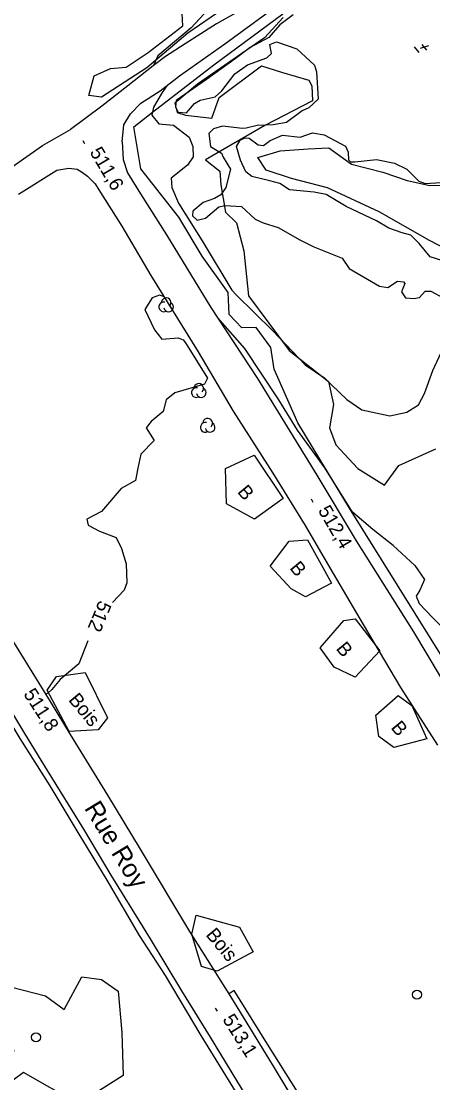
# Model space of a CAD drawing. Extents: x 347312 to 350503, y 6073086 to 6076432.
# Drawn here: x 348774 to 348863.2, y 6075462.2 to 6075692.2 of the extents above; entities that cross this region are included whole.
import ezdxf

# ---------------------------------------------------------------- set-up
doc = ezdxf.new("R2010")
doc.units = 0
for name, color, linetype in [('Level 1', 7, 'Continuous'), ('Level 2', 7, 'Continuous'), ('Level 21', 7, 'Continuous'), ('Level 22', 7, 'Continuous'), ('Level 3', 7, 'Continuous'), ('Level 36', 7, 'Continuous'), ('Level 4', 7, 'Continuous'), ('Level 44', 7, 'Continuous')]:
    doc.layers.add(name, color=color, linetype=linetype)

msp = doc.modelspace()

# ---------------------------------------------------------------- linework, layer by layer
at = {"layer": 'Level 1'}
for points in [[(348792.67, 6075717.75), (348797.14, 6075713.74), (348799.35, 6075711.05), (348800.45, 6075708.11), (348801.76, 6075705.87), (348803.97, 6075703.98), (348807.41, 6075702.03), (348811.66, 6075699.8), (348812.76, 6075698.76), (348814.14, 6075697.19), (348813.53, 6075693.76), (348810.82, 6075690.76), (348803.59, 6075684.69), (348802.71, 6075682.76), (348802.76, 6075682.69)], [(348805.5, 6075678.23), (348804.5, 6075676.72), (348802.64, 6075673.61), (348802.31, 6075671.83), (348803.82, 6075669.93), (348806.97, 6075669.68), (348810.36, 6075667.08), (348811.2, 6075665.07), (348811.24, 6075662.85), (348810.04, 6075661.03), (348806.44, 6075658.19), (348806.62, 6075656.16), (348808.04, 6075652.75), (348813.18, 6075644.61), (348819.65, 6075633.95), (348820.58, 6075632.93), (348828.51, 6075625.14), (348834.22, 6075619.11), (348835.5, 6075617.77), (348839.8, 6075614.87), (348841.31, 6075613.33), (348844.52, 6075610.21), (348847.78, 6075608.02), (348853.89, 6075606.68), (348857.51, 6075607.5), (348860.05, 6075609.08), (348861.34, 6075611.51), (348863.16, 6075616.48), (348865.94, 6075622.47)]]:
    msp.add_lwpolyline(points, dxfattribs=at)
at = {"layer": 'Level 2'}
for points in [[(348805, 6075632.44), (348803.94, 6075632.83), (348802.37, 6075632.27), (348800.78, 6075629.75), (348802.83, 6075625.3), (348804.46, 6075623.27), (348808.02, 6075623.6), (348809.06, 6075623.18), (348809.61, 6075622.51), (348814.37, 6075614.82), (348813.68, 6075613.57), (348807.29, 6075611.65), (348805.38, 6075610.15), (348804.74, 6075607.66), (348802.11, 6075605.48), (348801.03, 6075604.06), (348802.79, 6075601.32), (348799.88, 6075598.39), (348799.27, 6075595.32), (348798.74, 6075592.71), (348795.61, 6075590.94), (348791.41, 6075585.95), (348788.17, 6075584.32), (348788.46, 6075582.98), (348790.93, 6075581.73), (348794.54, 6075580.3), (348795.68, 6075577.94), (348796.73, 6075574.6), (348796.84, 6075570.49), (348796.28, 6075568.9), (348793.78, 6075566.23)], [(348854.6, 6075578.62), (348850.18, 6075582.02), (348845.8, 6075585.83), (348839.77, 6075595.4), (348833.86, 6075603.57), (348829.82, 6075610.13), (348822.46, 6075621.3), (348816.55, 6075627.95)], [(348854.6, 6075578.62), (348859.24, 6075574.25), (348861.34, 6075571.22), (348860.33, 6075568.93), (348859.57, 6075567.63), (348860.21, 6075566.05), (348863.1, 6075563.01), (348866.99, 6075559.08), (348871.48, 6075552.33), (348879.61, 6075540.67), (348884.92, 6075531.83), (348886.44, 6075529.65)], [(348788.4, 6075557.93), (348786.45, 6075552.94), (348782.39, 6075549.58), (348780.62, 6075547.36), (348779.73, 6075546.62), (348779.32, 6075546.4)]]:
    msp.add_lwpolyline(points, dxfattribs=at)
at = {"layer": 'Level 21'}
for points in [[(348820.43, 6075693.97), (348816.29, 6075691.6), (348809.51, 6075687.33), (348805.26, 6075684.55), (348802.56, 6075682.54), (348797.05, 6075678.2), (348791.45, 6075673.78), (348784.65, 6075668.74)], [(348795.88, 6075666.04), (348796.22, 6075669.74), (348797.63, 6075672.12), (348799.87, 6075674.42), (348804.07, 6075677.15), (348808.28, 6075680.34), (348818.12, 6075687.29), (348828.28, 6075694.74)], [(348619.66, 6075553.87), (348630.41, 6075564.21), (348642.32, 6075573.7), (348654.32, 6075582.45), (348666.87, 6075591.81), (348671.89, 6075594.95), (348677.61, 6075598.53), (348683.84, 6075602.72), (348697.14, 6075610.9), (348710.9, 6075619.61), (348726.09, 6075629.95), (348739.55, 6075638.85), (348753.52, 6075648.41), (348766.38, 6075656.75), (348778.57, 6075665.28), (348784.65, 6075668.74)], [(348795.88, 6075666.04), (348796.06, 6075662.21), (348797.02, 6075659.33), (348799.81, 6075654.82), (348805.45, 6075645.9), (348815.1, 6075630.18), (348825.15, 6075614.78), (348838.03, 6075593.86), (348846.54, 6075579.59), (348858.99, 6075559.88), (348870.32, 6075540.88), (348878.71, 6075527.02), (348888.64, 6075510.69), (348898.24, 6075494.76), (348906.45, 6075482.02), (348910.6, 6075477.5), (348912.89, 6075476.47), (348924.17, 6075478.22), (348938.88, 6075486.8), (348955.83, 6075497.3), (348969.56, 6075505.52), (348975.65, 6075508.61), (348976.73, 6075508.67), (348977.96, 6075508.19)], [(348773.4, 6075654.7), (348781.7, 6075659.93), (348784.29, 6075660.35), (348786.08, 6075660.11), (348787.25, 6075659.43), (348788.32, 6075658.59), (348789.98, 6075656.97), (348790.77, 6075655.67), (348795.75, 6075647.79), (348802.09, 6075637.13), (348812.36, 6075620.57), (348819.93, 6075607.7), (348828.48, 6075594.29), (348835.49, 6075582.9), (348840.85, 6075573.76), (348848.07, 6075561.5), (348856.15, 6075547.84), (348864.2, 6075535.29)], [(348836.72, 6075452.34), (348828.46, 6075466.15), (348820.81, 6075478.58), (348819.03, 6075481.41), (348810.51, 6075494.91), (348799.83, 6075512.79), (348792.73, 6075524.47), (348784.65, 6075537.6), (348780.34, 6075544.76), (348769.89, 6075561.63)], [(348822.91, 6075458.94), (348815.03, 6075472.01), (348808.76, 6075482.06), (348801.99, 6075493.35), (348793.44, 6075507.13), (348787.54, 6075517.11), (348779.67, 6075529.81), (348774.78, 6075537.84), (348769.21, 6075547.05)]]:
    msp.add_lwpolyline(points, dxfattribs=at)
at = {"layer": 'Level 22'}
for points in [[(348837.61, 6075425.75), (348836.85, 6075426.95), (348838.29, 6075428.37), (348838.53, 6075429.25), (348838.45, 6075430.53), (348835.14, 6075436.13), (348828.18, 6075447.56), (348820.39, 6075460.34), (348812.99, 6075472.38), (348805.23, 6075485.39), (348799.62, 6075494.11), (348792.63, 6075506.03), (348786.31, 6075516.42), (348780.25, 6075526.49), (348773.72, 6075536.76), (348766.95, 6075547.96), (348764.72, 6075551), (348763.64, 6075551.84), (348762.61, 6075552.18), (348761.64, 6075552.35), (348760.24, 6075551.94), (348756.72, 6075549.93), (348749.31, 6075544.99), (348744.96, 6075541.98)], [(348901.69, 6075464.54), (348900.87, 6075465.84), (348895.33, 6075462.45), (348884.32, 6075455.81), (348874.88, 6075449.87), (348864.55, 6075443.73), (348853.03, 6075436.67), (348850.81, 6075435.72), (348850.11, 6075435.75), (348849.01, 6075436.26), (348848.15, 6075437.2), (348847.06, 6075438.41), (348840.37, 6075449.16), (348834.18, 6075459.65), (348826.97, 6075471.1), (348820.1, 6075482.15), (348819.03, 6075481.41)]]:
    msp.add_lwpolyline(points, dxfattribs=at)
at = {"layer": 'Level 3'}
for p, q in [((348859.13, 6075686.67), (348860.15, 6075685.44)), ((348862.23, 6075686.84), (348860.4, 6075686.29)), ((348860.81, 6075687.15), (348861.8, 6075685.95)), ((348787.3, 6075666.37), (348787.71, 6075665.68)), ((348836.78, 6075588.69), (348837.19, 6075588)), ((348816, 6075478.36), (348816.43, 6075477.68))]:
    msp.add_line(p, q, dxfattribs=at)
at = {"layer": 'Level 36'}
for centre in [(348859.74, 6075481.26), (348777.19, 6075472.01)]:
    msp.add_circle(centre, 1, dxfattribs=at)
at = {"layer": 'Level 4'}
for points in [[(348832.88, 6075693.57), (348830.04, 6075691.44), (348827.64, 6075688.71), (348823.6, 6075686.48), (348820.33, 6075684.07), (348814.14, 6075679.54), (348807.58, 6075675), (348807.4, 6075673.58), (348808, 6075672.5), (348809.8, 6075672.34), (348811.51, 6075674.36), (348812.78, 6075675.1)], [(348812.78, 6075675.1), (348816.02, 6075675.84), (348817.46, 6075677.1), (348820.24, 6075680.83), (348823.05, 6075682.72), (348827.19, 6075684.27), (348828.23, 6075685.2), (348827.83, 6075687.13), (348829.28, 6075687.73), (348833.72, 6075686.22), (348837.51, 6075682.68), (348837.96, 6075681.24), (348838.36, 6075675.33), (348836.29, 6075673.46), (348834.87, 6075672.81), (348831.46, 6075670.29), (348828.6, 6075669.72), (348825.13, 6075669.63), (348825.13, 6075669.63), (348822.69, 6075669.03), (348821.9, 6075668.98), (348817.62, 6075669.49), (348815.62, 6075668.89), (348814.66, 6075667.87), (348814.98, 6075665.05), (348817.4, 6075663.59), (348817.73, 6075662.74), (348819.3, 6075660.14), (348818.32, 6075656.16), (348817.27, 6075654.61), (348815.87, 6075653.75), (348813.4, 6075652.91), (348811.17, 6075651.06), (348811.11, 6075650.04), (348812.14, 6075649.08), (348813.91, 6075649.49), (348816.82, 6075651.98), (348818.16, 6075652.27), (348821.73, 6075652.07), (348824.69, 6075649.33), (348826.43, 6075648.52), (348829.68, 6075647.53), (348834.34, 6075644.84), (348837.37, 6075643.29), (348843.54, 6075640.88), (348845.02, 6075638.65), (348851.59, 6075634.77), (348853.42, 6075634.48), (348855.52, 6075635.85), (348856.83, 6075635.73), (348857.13, 6075635.37), (348856.35, 6075633.59)], [(348865.09, 6075640.32), (348862.57, 6075641.16), (348860.2, 6075644.01), (348858.43, 6075645.85), (348856.5, 6075646.36), (348853.62, 6075647.36), (348851, 6075648.95), (348844.36, 6075652.02), (348840.03, 6075654.68), (348837.44, 6075655.16), (348832.12, 6075655.64), (348830.03, 6075657.07), (348827.85, 6075657.59), (348823.94, 6075658.56), (348822.67, 6075659.54), (348821.51, 6075662.11), (348820.66, 6075665.02), (348821.45, 6075666.43), (348822.45, 6075666.96), (348823.39, 6075666.83), (348825.36, 6075665.38), (348826.5, 6075665.27), (348827.92, 6075666.38), (348830.62, 6075667.49), (348834.46, 6075667.06), (348837.11, 6075668.05), (348839.66, 6075667.61), (348844.22, 6075665.14), (348844.84, 6075663.85), (348844.93, 6075662.2), (348845.31, 6075661.76), (348846.29, 6075661.75), (348850.96, 6075662.23), (348854.84, 6075661.46), (348857.56, 6075660.11), (348860.13, 6075657.57), (348861.52, 6075657), (348864.97, 6075657.22)], [(348856.35, 6075633.59), (348857.25, 6075632.24), (348859.06, 6075632.15), (348860.27, 6075632.33), (348861.55, 6075633.69), (348862.75, 6075633.71), (348865.42, 6075632.23)]]:
    msp.add_lwpolyline(points, dxfattribs=at)
at = {"layer": 'Level 44'}
for points in [[(348827.8, 6075701.84), (348810.09, 6075689.62), (348801.19, 6075682.1), (348791.35, 6075675.74), (348788.66, 6075676.14), (348789.8, 6075680.38), (348793.32, 6075681.95), (348796.69, 6075682.27), (348801.51, 6075685.42), (348808.99, 6075691.19), (348808.62, 6075697.79)], [(348869.77, 6075547.19), (348845.11, 6075586.68), (348833.9, 6075605.2), (348828.76, 6075616.83), (348828.04, 6075621.49), (348824.9, 6075625.8), (348821.77, 6075625.76), (348819.07, 6075628.63), (348818.86, 6075633.4), (348813.17, 6075641.31), (348808.1, 6075649.73), (348799.87, 6075660.2), (348798.37, 6075669.31), (348802.45, 6075672.46), (348815.69, 6075682.75), (348830.66, 6075693.83)], [(348830.76, 6075693.02), (348826.72, 6075688.62), (348812.19, 6075678.53), (348807.28, 6075674.46), (348807.75, 6075672.44), (348809.59, 6075671.87), (348815.3, 6075671.18), (348816.86, 6075675.64), (348826.07, 6075682.52), (348830.39, 6075681.14), (348836.34, 6075679.45), (348836.96, 6075678.17), (348837.07, 6075674.95), (348826.77, 6075669.57), (348813.89, 6075662.2), (348817.03, 6075659.7), (348817.25, 6075656.72), (348818.27, 6075650.8), (348820.61, 6075648.53), (348822.19, 6075642.47), (348823.26, 6075632.69), (348832.06, 6075620.88), (348840.58, 6075614.11), (348841.68, 6075609.16), (348840.8, 6075604.07), (348842.19, 6075600.41), (348846.93, 6075595.3)], [(348868.61, 6075641.48), (348862.43, 6075644.66), (348851.55, 6075650.89), (348840.36, 6075656.07), (348832.55, 6075658.11), (348827.09, 6075659.93), (348825.22, 6075662.7), (348830.1, 6075664.1), (348836.14, 6075664.56), (348840.65, 6075664.8), (348845.53, 6075661.21), (348852.37, 6075659.47), (348857.6, 6075657.67), (348862.5, 6075656.63), (348869.85, 6075656.73)], [(348846.93, 6075595.3), (348852.69, 6075591.65), (348855.8, 6075595.89), (348863.81, 6075599.51)], [(348830.74, 6075588.79), (348824.56, 6075584.27), (348818.46, 6075587.62), (348818.26, 6075595.26), (348824.45, 6075598.14), (348830.74, 6075588.79)], [(348841.21, 6075570.46), (348835.59, 6075567.45), (348832.46, 6075569.21), (348827.9, 6075574.14), (348832.02, 6075579.5), (348835.99, 6075579.79), (348841.21, 6075570.46)], [(348851.69, 6075555.73), (348846.31, 6075550.07), (348841.82, 6075552.21), (348838.76, 6075556.42), (348843.91, 6075562.34), (348846.33, 6075562.7), (348851.69, 6075555.73)], [(348787.84, 6075551.05), (348792.69, 6075541.26), (348790.63, 6075538.66), (348784.35, 6075538.25), (348779.58, 6075547.21), (348781.59, 6075550.23), (348787.84, 6075551.05)], [(348861.85, 6075536.68), (348854.69, 6075534.8), (348851.46, 6075537.23), (348850.81, 6075541.79), (348855.65, 6075546.1), (348858.66, 6075543.94), (348861.85, 6075536.68)], [(348811.92, 6075498.49), (348821.3, 6075495.9), (348824.26, 6075490.54), (348816.47, 6075486.34), (348813.03, 6075487.39), (348810.96, 6075494.39), (348811.92, 6075498.49)], [(348744.72, 6075459.58), (348746.47, 6075463.44), (348757.32, 6075462.52), (348764.08, 6075463.62), (348772.48, 6075469.08), (348766.23, 6075479.65), (348771.63, 6075482.93), (348779.26, 6075481), (348783.26, 6075478.01), (348787.13, 6075485.11), (348791.35, 6075484.56), (348794.98, 6075482.01), (348795.79, 6075473.08), (348796.08, 6075463.71), (348786.39, 6075457.63), (348774.44, 6075464.39), (348770.55, 6075461.47)]]:
    msp.add_lwpolyline(points, dxfattribs=at)
for centre, start, end in [((348804.87, 6075630.3), 76.8848, 299.5691), ((348805.39, 6075631.2), 314.0633, 179.7519), ((348805.92, 6075630.3), 192.2171, 59.6742), ((348811.93, 6075611.73), 76.8848, 299.5691), ((348812.45, 6075612.63), 314.0633, 179.7519), ((348812.98, 6075611.73), 192.2171, 59.6742), ((348814.38, 6075605.09), 314.0633, 179.7519), ((348813.86, 6075604.19), 76.8848, 299.5691), ((348814.91, 6075604.19), 192.2171, 59.6742)]:
    msp.add_arc(centre, 1.05, start, end, dxfattribs=at)

# ---------------------------------------------------------------- texts
at = {"layer": 'Level 2'}
msp.add_text('512', height=3, rotation=247.415, dxfattribs=at).set_placement((348790.89, 6075566.86))
at = {"layer": 'Level 21'}
msp.add_text('Rue Roy', height=4, rotation=301.0454, dxfattribs=at).set_placement((348787.54, 6075521.68))
at = {"layer": 'Level 3'}
for s, rotation, p in [('511,6', 300.3903, (348788.73, 6075663.86)), ('512,4', 300.3998, (348838.21, 6075586.19)), ('511,8', 302.865, (348774.36, 6075546.42)), ('513,1', 302.093, (348817.5, 6075475.9))]:
    msp.add_text(s, height=3, rotation=rotation, dxfattribs=at).set_placement(p)
at = {"layer": 'Level 44'}
for s, p in [('B', (348820.68, 6075590.17)), ('B', (348832.01, 6075573.65)), ('B', (348842.06, 6075556.19)), ('Bois', (348784.07, 6075545.08)), ('B', (348853.95, 6075539.07)), ('Bois', (348813.83, 6075494.18))]:
    msp.add_text(s, height=3, rotation=309.568, dxfattribs=at).set_placement(p)

doc.saveas('drawing.dxf')
